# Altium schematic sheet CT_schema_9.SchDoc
size 147 x 119 mm
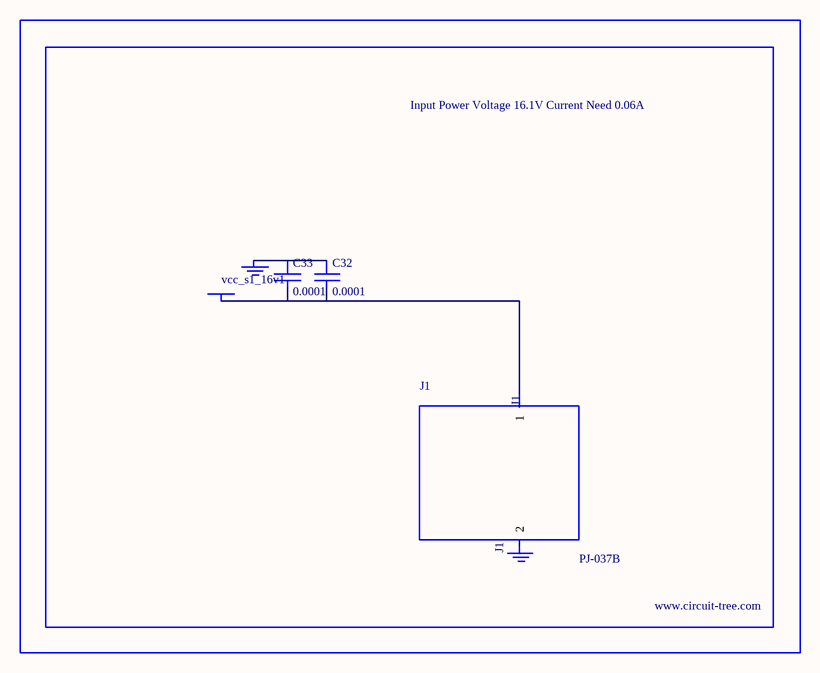
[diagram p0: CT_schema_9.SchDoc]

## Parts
BORDER8  (no value)
C32  0.0001  [EXV-9H]
C33  0.0001  [EXV-9H]
GND_INSTANCE_8_0  (no value)
GND_INSTANCE_8_1  (no value)
J1  PJ-037B  [PJ-037B_PACKAGE]
POWER_INSTANCE_8_0  vcc_s1_16v1

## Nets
NetC32_1: C32.1 C33.1 GND_INSTANCE_8_0.0(GND)
NetC32_2: C32.2 C33.2 J1.1 POWER_INSTANCE_8_0.0(PWR)

Not connected (* = marked no-connect by the designer): GND_INSTANCE_8_1 0(GND); J1 2

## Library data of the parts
BORDER8 = BORDER_PAGE8
C32 C33 = EDK107M035A9HAA
GND_INSTANCE_8_0 GND_INSTANCE_8_1 = GND
POWER_INSTANCE_8_0 = PWR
